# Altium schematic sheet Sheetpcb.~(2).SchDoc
size A; SheetNumber: 2; SheetTotal: 2
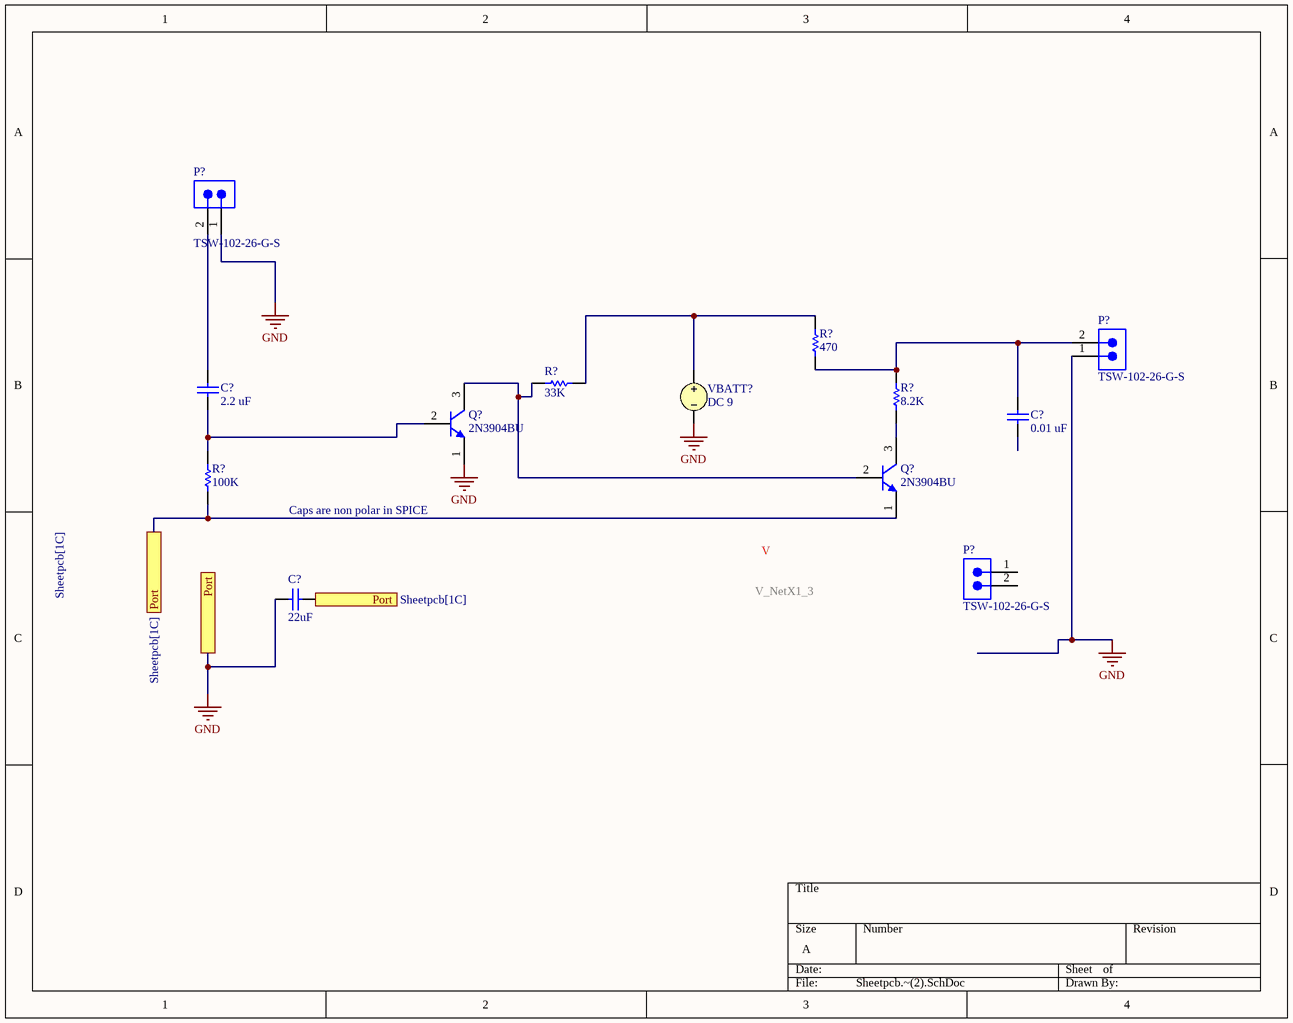
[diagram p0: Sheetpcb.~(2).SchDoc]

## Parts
(Parts that share a designator on the sheet are numbered #1, #2 ... from top to bottom, then left to right.)
C?#1  value 2.2 uF  (hidden comment: Capacitor)
C?#2  value 0.01 uF  (hidden comment: Capacitor)
C?#3  value 22uF  (hidden comment: Capacitor)
P?#1  TSW-102-26-G-S  [SMTC-TSW-102-26-XX-S]
P?#2  TSW-102-26-G-S  [SMTC-TSW-102-26-XX-S]
P?#3  TSW-102-26-G-S  [SMTC-TSW-102-26-XX-S]
Q?#1  2N3904BU  [FAIR-TO-92]
Q?#2  2N3904BU  [FAIR-TO-92]
R?#1  value 470  (hidden comment: Resistor)
R?#2  value 8.2K  (hidden comment: Resistor)
R?#3  value 33K  (hidden comment: Resistor)
R?#4  value 100K  (hidden comment: Resistor)
VBATT?  DC 9

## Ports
Port (see Sheetpcb[1C])

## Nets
GND: C?#3.1 C?#3.2 P?#1.1 P?#2.1 Q?#1.1(E) Q?#2.1(E) R?#4.1 VBATT?.2 ; port Port
NetC?#1_1: C?#1.1 Q?#1.2(B) R?#4.2
NetC?#1_2: C?#1.2 P?#1.2
NetC?#2_2: C?#2.2 P?#2.2 R?#1.1 R?#2.1
NetQ?#1_3: Q?#1.3(C) Q?#2.2(B) R?#3.2
NetQ?#2_3: Q?#2.3(C) R?#2.2
NetR?#1_2: R?#1.2 R?#3.1 VBATT?.1

Not connected (* = marked no-connect by the designer): C?#2 1; P?#3 1 2

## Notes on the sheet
- Caps are non polar in SPICE

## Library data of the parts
C?#1-C?#3 = Capacitor: SimulationGenericComponent: True
P?#1-P?#3 = CMP-1024-00327-1: 0.025" SQ Post Header, Through-hole, Vertical, -55 to 125 degC, 2.54 mm Pitch, 2-Pin, Male, RoHS; Manufacturer: Samtec; Pitch: 2.54 mm
Q?#1 Q?#2 = CMP-2000-04944-1: NPN General-Purpose Amplifier, 40 V VCEO, 0.2 A, -55 to 150 degC, 2-Pin TO-92, RoHS, Bulk; Manufacturer: FairchildSemiconductor; Maximum Collector Base Voltage: 60V; Minimum DC Current Gain: 40@0.1mA@1V; Maximum Collector Emitter Voltage: 40V; Maximum DC Collector Current: 0.2A; Rad Hard: No; Maximum Operating Frequency: 300(Min)MHz; Maximum Collector Emitter Saturation Voltage: 0.2@1mA@10mA; Maximum Power Dissipation: 625mW
R?#1-R?#4 = Resistor: TC1: 0; SimulationGenericComponent: True
VBATT? = VSRC: Voltage Source; Note: PCB Footprint - Not required; AC Magnitude: 1; AC Phase: 0; Value: 9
